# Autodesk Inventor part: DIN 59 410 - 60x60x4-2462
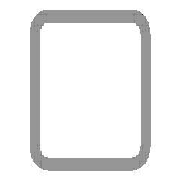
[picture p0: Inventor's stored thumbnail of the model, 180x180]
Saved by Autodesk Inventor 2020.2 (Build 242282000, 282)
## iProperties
Manager: www.cadconsulting.pl
Company: Fabian Stasiak CAD Consulting
IsCustomPart: 1
_CCFamilyMember: 60
_CCFamilyDisplayName: DIN 59410 (Kwadrat) - Rurki stalowe o przekroju kwadratowym formowane na gorąco
_FrameMemberDoc: Frame Member File
_Version: 15.0.0
_GetPNFromCC: 1
Created: 2015-01
Part Number: DIN 59 410 - 60x60x4-2462
Material: Stal, miękka
Description: Rurki stalowe o przekroju kwadratowym formowane na gorąco
Document SubType Name: Modellieren
Standard: DIN
Designer: F.Stasiak
Standards Organization: DIN
Language: pl-PL
Size Designation: 60x60x4
Categories: <MemberInstance><Categories><Category DisplayName="Kształtowniki konstrukcyjne" InternalName="089c4875-fa83-4c05-b084-43b9cc11f5ed" Mnemonic="GRDR"><CategoryPar
Stock Number: 60x60x4
Density: 7.85 g/cm^3
Appearance: Częściowo polerowana
Catalog Web Link: www.expertbooks.pl
G_L: 2462,000 mm
G_W: 60,000 mm
G_H: 60,000 mm
+17F8051A-2EA8-44DE-A580-A9D3ECAA54A9+CUTDETAIL1: Wytnij
Author: F.Stasiak
Subject: Zbiór ćwiczeń. Autodesk Inventor 2020. Kurs Professional
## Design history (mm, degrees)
node "Płaszczyzna początkowa"
node "Płaszczyzna końcowa"
sketch "Szkic1"
  geometry: L1 (-22, 30)-(22, 30); L2 (30, 22)-(30, -22); L3 (22, -30)-(-22, -30); L4 (-30, -22)-(-30, 22); L5 (-44.32, 0)-(44.32, 0) reference; L6 (0, -44.32)-(0, 44.32) reference; L7 (-22, 26)-(22, 26); L8 (26, 22)-(26, -22); L9 (22, -26)-(-22, -26); L10 (-26, -22)-(-26, 22); A1 r 8 centre (-22, 22) between (-22, 30) and (-30, 22); A2 r 8 centre (22, 22) between (30, 22) and (22, 30); A3 r 8 centre (22, -22) between (22, -30) and (30, -22); A4 r 8 centre (-22, -22) between (-30, -22) and (-22, -30); A5 r 4 centre (-22, 22) between (-22, 26) and (-26, 22); A6 r 4 centre (22, 22) between (26, 22) and (22, 26); A7 r 4 centre (22, -22) between (22, -26) and (26, -22); A8 r 4 centre (-22, -22) between (-26, -22) and (-22, -26); 3 further points
  constraints: 16 end point, 16 point on circle, 8 centre point, 8 tangent, 6 point on line, 4 parallel, 3 equal radius, 3 perpendicular, 1 horizontal, 7 other
  dimensions: "b" = 60 distance of point (-30, 30) point (30, 30); "msp_r" = 8 radius of A1 (= 2 x ParT); "d8" = 30 distance between parallel lines of L4 L6 (= d9); "d9" = 30 distance between parallel lines of L3 L5 (= 0.5 x b); "d10" = 4 distance between parallel lines of L3 L9 (= ParT)
extrude "Bryła" new body sketch "Szkic1" taper "d4" = 0 deg; stored distance "NLG" = 10
node "Driven Length"
  sketch "Sketch2"
    geometry: L1 (0, 0)-(10, 0) reference
    constraints: 2 end point, 1 horizontal
  workplane "Work Plane3"
  sketch "Sketch3"
    geometry: L1 (-2, 38)-(12, 38) reference; L2 (-2, 2500)-(12, 2500) reference
    dimensions: "d14" = 2462 distance between parallel lines of L1 L2 (derived)
node "Płaszczyzna konstrukcyjna4"
feature "Podział1"
body "Solid1"
other parameters: "ParT" = 4, "G_OFFSET_START" = -38 [user parameter; used in 1 equation term], "G_OFFSET_END" = 0 [user parameter; used in 1 equation term], "d11" = 38 (= -G_OFFSET_START), "G_L" = 2462 (= d14) [user parameter], "d13" = 90 deg
